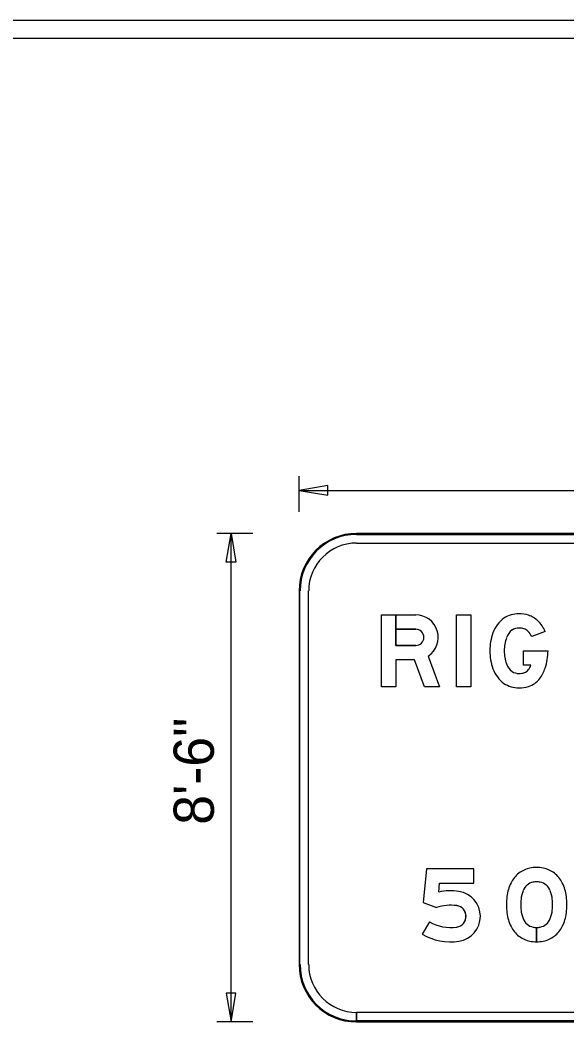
# Model space of a CAD drawing. Extents: x 10268147 to 10268469, y 2141099 to 2141204.
# Drawn here: x 10268267.89 to 10268277.41, y 2141186.52 to 2141203.96 of the extents above; entities that cross this region are included whole.
import ezdxf

# ---------------------------------------------------------------- set-up
doc = ezdxf.new("R2010")
doc.units = 0
for name, color, linetype in [('61', 7, 'Continuous'), ('GSDims', 7, 'Continuous'), ('PlotBorder_dp', 7, 'Continuous'), ('SheetLinesMisc2_dp', 7, 'Continuous')]:
    doc.layers.add(name, color=color, linetype=linetype)

msp = doc.modelspace()

# ---------------------------------------------------------------- linework, layer by layer
at = {"layer": '61'}
msp.add_line((10268230.252, 2141203.638), (10268305.587, 2141203.638), dxfattribs=at)
at = {"layer": 'GSDims'}
for p, q in [((10268272.747, 2141195.396), (10268272.747, 2141196.021)), ((10268272.747, 2141195.771), (10268287.747, 2141195.771)), ((10268271.941, 2141195.021), (10268271.316, 2141195.021)), ((10268271.566, 2141186.521), (10268271.566, 2141195.021)), ((10268271.941, 2141186.521), (10268271.316, 2141186.521))]:
    msp.add_line(p, q, dxfattribs=at)
for points in [[(10268272.747, 2141195.771), (10268273.247, 2141195.688), (10268273.247, 2141195.855)], [(10268271.566, 2141195.021), (10268271.649, 2141194.521), (10268271.482, 2141194.521)], [(10268271.566, 2141186.521), (10268271.649, 2141187.021), (10268271.482, 2141187.021)]]:
    msp.add_lwpolyline(points, close=True, dxfattribs=at)
at = {"layer": 'PlotBorder_dp'}
for p, q in [((10268286.748, 2141195.021), (10268273.748, 2141195.021)), ((10268286.748, 2141195.021), (10268273.748, 2141195.021)), ((10268286.748, 2141195.021), (10268273.748, 2141195.021)), ((10268286.748, 2141195.021), (10268273.748, 2141195.021)), ((10268273.748, 2141195.004), (10268286.748, 2141195.004)), ((10268273.748, 2141194.854), (10268286.748, 2141194.854)), ((10268273.748, 2141194.854), (10268286.748, 2141194.854)), ((10268272.748, 2141194.021), (10268272.748, 2141187.521)), ((10268272.748, 2141194.021), (10268272.748, 2141187.521)), ((10268272.748, 2141194.021), (10268272.748, 2141187.521)), ((10268272.748, 2141194.021), (10268272.748, 2141187.521)), ((10268272.764, 2141187.521), (10268272.764, 2141194.021)), ((10268272.914, 2141187.521), (10268272.914, 2141194.021)), ((10268272.914, 2141187.521), (10268272.914, 2141194.021)), ((10268275.014, 2141188.265), (10268274.889, 2141188.048)), ((10268275.014, 2141188.265), (10268274.889, 2141188.048)), ((10268275.014, 2141188.265), (10268274.889, 2141188.048)), ((10268276.88, 2141188.166), (10268276.88, 2141187.916)), ((10268276.88, 2141187.916), (10268276.88, 2141188.166)), ((10268276.88, 2141188.166), (10268276.88, 2141187.916)), ((10268276.88, 2141187.916), (10268276.88, 2141188.166)), ((10268273.748, 2141186.521), (10268273.748, 2141186.688)), ((10268273.748, 2141186.521), (10268273.748, 2141186.688)), ((10268286.748, 2141186.688), (10268273.749, 2141186.688)), ((10268273.749, 2141186.688), (10268273.749, 2141186.521)), ((10268286.748, 2141186.688), (10268273.749, 2141186.688)), ((10268273.749, 2141186.688), (10268273.749, 2141186.521)), ((10268273.748, 2141186.521), (10268273.748, 2141186.538)), ((10268286.748, 2141186.538), (10268273.748, 2141186.538)), ((10268273.748, 2141186.538), (10268273.748, 2141186.521)), ((10268273.748, 2141186.521), (10268286.748, 2141186.521)), ((10268273.748, 2141186.521), (10268286.748, 2141186.521)), ((10268273.749, 2141186.521), (10268286.748, 2141186.521)), ((10268273.749, 2141186.521), (10268286.748, 2141186.521))]:
    msp.add_line(p, q, dxfattribs=at)
for points in [[(10268274.995, 2141192.888), (10268275.193, 2141192.355), (10268274.927, 2141192.355), (10268274.753, 2141192.822), (10268274.431, 2141192.822), (10268274.431, 2141192.355), (10268274.181, 2141192.355), (10268274.181, 2141193.605), (10268274.431, 2141193.605), (10268274.431, 2141193.072)], [(10268274.995, 2141192.888), (10268275.193, 2141192.355), (10268274.927, 2141192.355), (10268274.753, 2141192.822), (10268274.431, 2141192.822), (10268274.431, 2141192.355), (10268274.181, 2141192.355), (10268274.181, 2141193.605), (10268274.431, 2141193.605), (10268274.431, 2141193.072)], [(10268274.995, 2141192.888), (10268275.193, 2141192.355), (10268274.927, 2141192.355), (10268274.753, 2141192.822), (10268274.431, 2141192.822), (10268274.431, 2141192.355), (10268274.181, 2141192.355), (10268274.181, 2141193.605), (10268274.777, 2141193.605)], [(10268274.777, 2141193.355), (10268274.431, 2141193.355), (10268274.431, 2141193.605), (10268274.777, 2141193.605)], [(10268274.777, 2141193.355), (10268274.431, 2141193.355), (10268274.431, 2141193.605), (10268274.777, 2141193.605)], [(10268274.777, 2141193.072), (10268274.431, 2141193.072), (10268274.431, 2141193.355), (10268274.777, 2141193.355)], [(10268277.028, 2141193.315), (10268276.794, 2141193.226)], [(10268277.028, 2141193.315), (10268276.794, 2141193.226)], [(10268277.028, 2141193.315), (10268276.794, 2141193.226)], [(10268274.431, 2141193.072), (10268274.777, 2141193.072)], [(10268274.431, 2141193.072), (10268274.777, 2141193.072)], [(10268276.78, 2141192.73), (10268276.65, 2141192.73), (10268276.65, 2141192.98), (10268277.078, 2141192.98)], [(10268276.78, 2141192.73), (10268276.65, 2141192.73), (10268276.65, 2141192.98), (10268277.078, 2141192.98)], [(10268276.78, 2141192.73), (10268276.65, 2141192.73), (10268276.65, 2141192.98), (10268277.078, 2141192.98)], [(10268275.177, 2141188.78), (10268275.193, 2141188.937), (10268275.789, 2141188.937), (10268275.789, 2141189.187), (10268274.967, 2141189.187), (10268274.908, 2141188.6), (10268275.138, 2141188.51)], [(10268275.177, 2141188.78), (10268275.193, 2141188.937), (10268275.789, 2141188.937), (10268275.789, 2141189.187), (10268274.967, 2141189.187), (10268274.908, 2141188.6), (10268275.138, 2141188.51)], [(10268275.177, 2141188.78), (10268275.193, 2141188.937), (10268275.789, 2141188.937), (10268275.789, 2141189.187), (10268274.967, 2141189.187), (10268274.908, 2141188.6), (10268275.138, 2141188.51)]]:
    msp.add_lwpolyline(points, dxfattribs=at)
msp.add_lwpolyline([(10268275.484, 2141193.605), (10268275.734, 2141193.605), (10268275.734, 2141192.355), (10268275.484, 2141192.355)], close=True, dxfattribs=at)
msp.add_lwpolyline([(10268275.484, 2141193.605), (10268275.734, 2141193.605), (10268275.734, 2141192.355), (10268275.484, 2141192.355)], close=True, dxfattribs=at)
msp.add_lwpolyline([(10268275.484, 2141193.605), (10268275.734, 2141193.605), (10268275.734, 2141192.355), (10268275.484, 2141192.355)], close=True, dxfattribs=at)
for centre, radius, start, end in [((10268273.748, 2141194.021), 1, 90, 180), ((10268273.748, 2141194.021), 1, 90, 180), ((10268273.748, 2141194.021), 1, 90, 180), ((10268273.748, 2141194.021), 1, 90, 180), ((10268273.748, 2141194.021), 0.983, 90, 180), ((10268273.748, 2141194.021), 0.833, 90, 180), ((10268273.748, 2141194.021), 0.833, 90, 180), ((10268273.748, 2141187.521), 1, 180, 270), ((10268273.748, 2141187.521), 1, 180, 270), ((10268273.748, 2141187.521), 1, 180, 270), ((10268273.748, 2141187.521), 1, 180, 270), ((10268273.748, 2141187.521), 0.983, 180, 270), ((10268273.748, 2141187.521), 0.833, 180, 270), ((10268273.748, 2141187.521), 0.833, 180, 270)]:
    msp.add_arc(centre, radius, start, end, dxfattribs=at)
for centre, major_axis, ratio, start_param, end_param in [((10268274.777, 2141193.213), (0, 0.391), 0.999998, 3.731228, 6.283185), ((10268274.777, 2141193.213), (0, 0.391), 0.999998, 3.731228, 6.283185), ((10268274.777, 2141193.213), (0, 0.391), 0.999998, 3.731228, 6.283185), ((10268276.634, 2141193.109), (0, 0.545), 0.999996, 0.634329, 1.227998), ((10268276.634, 2141193.109), (0, 0.545), 0.999996, 0.634329, 1.227998), ((10268276.634, 2141193.109), (0, 0.545), 0.999996, 0.634329, 1.227998), ((10268276.571, 2141193.145), (0, 0.479), 0.999996, 6.282946, 6.85835), ((10268276.571, 2141193.145), (0, 0.479), 0.999996, 6.282946, 6.85835), ((10268276.571, 2141193.145), (0, 0.479), 0.999996, 6.282946, 6.85835), ((10268276.571, 2141193.087), (0, 0.537), 0.999996, 5.968128, 6.283185), ((10268276.571, 2141193.087), (0, 0.537), 0.999996, 5.968128, 6.283185), ((10268276.571, 2141193.087), (0, 0.537), 0.999996, 5.968128, 6.283185), ((10268276.606, 2141193.194), (0, 0.425), 0.999996, 5.51497, 5.968128), ((10268276.606, 2141193.194), (0, 0.425), 0.999996, 5.51497, 5.968128), ((10268276.606, 2141193.194), (0, 0.425), 0.999996, 5.51497, 5.968128), ((10268276.571, 2141193.145), (0, 0.229), 0.999996, 6.282815, 6.826868), ((10268276.571, 2141193.145), (0, 0.229), 0.999996, 6.282815, 6.826868), ((10268276.571, 2141193.145), (0, 0.229), 0.999996, 6.282815, 6.826868), ((10268276.571, 2141193.087), (0, 0.287), 0.999996, 5.968128, 6.283185), ((10268276.571, 2141193.087), (0, 0.287), 0.999996, 5.968128, 6.283185), ((10268276.571, 2141193.087), (0, 0.287), 0.999996, 5.968128, 6.283185), ((10268276.513, 2141193.097), (0, 0.559), 0.999996, 5.112302, 5.51497), ((10268276.513, 2141193.097), (0, 0.559), 0.999996, 5.112302, 5.51497), ((10268276.513, 2141193.097), (0, 0.559), 0.999996, 5.112302, 5.51497), ((10268274.777, 2141193.213), (0, 0.141), 0.999998, 3.141593, 6.283185), ((10268274.777, 2141193.213), (0, 0.141), 0.999998, 3.141593, 6.283185), ((10268274.777, 2141193.213), (0, 0.141), 0.999998, 3.141593, 6.283185), ((10268277.053, 2141192.965), (0, 0.988), 0.999996, 1.233536, 1.555728), ((10268277.053, 2141192.965), (0, 0.988), 0.999996, 1.233536, 1.555728), ((10268277.053, 2141192.965), (0, 0.988), 0.999996, 1.233536, 1.555728), ((10268276.998, 2141192.979), (0, 0.681), 0.999996, 1.228714, 1.570494), ((10268276.998, 2141192.979), (0, 0.681), 0.999996, 1.228714, 1.570494), ((10268276.998, 2141192.979), (0, 0.681), 0.999996, 1.228714, 1.570494), ((10268276.634, 2141193.109), (0, 0.295), 0.999996, 0.660238, 1.227998), ((10268276.634, 2141193.109), (0, 0.295), 0.999996, 0.660238, 1.227998), ((10268276.634, 2141193.109), (0, 0.295), 0.999996, 0.660238, 1.227998), ((10268276.606, 2141193.194), (0, 0.175), 0.999996, 5.51497, 5.968128), ((10268276.606, 2141193.194), (0, 0.175), 0.999996, 5.51497, 5.968128), ((10268276.606, 2141193.194), (0, 0.175), 0.999996, 5.51497, 5.968128), ((10268276.513, 2141193.097), (0, 0.309), 0.999996, 5.141395, 5.51497), ((10268276.513, 2141193.097), (0, 0.309), 0.999996, 5.141395, 5.51497), ((10268276.513, 2141193.097), (0, 0.309), 0.999996, 5.141395, 5.51497), ((10268277.053, 2141192.994), (0, 0.988), 0.999996, 1.585865, 1.908057), ((10268277.053, 2141192.994), (0, 0.988), 0.999996, 1.585865, 1.908057), ((10268277.053, 2141192.994), (0, 0.988), 0.999996, 1.585865, 1.908057), ((10268276.997, 2141192.98), (0, 0.681), 0.999996, 1.571362, 1.913142), ((10268276.997, 2141192.98), (0, 0.681), 0.999996, 1.571362, 1.913142), ((10268276.997, 2141192.98), (0, 0.681), 0.999996, 1.571362, 1.913142), ((10268276.163, 2141192.98), (0, 0.915), 0.999996, 4.373891, 4.712389), ((10268276.163, 2141192.98), (0, 0.915), 0.999996, 4.373891, 4.712389), ((10268276.163, 2141192.98), (0, 0.915), 0.999996, 4.373891, 4.712389), ((10268276.633, 2141192.85), (0, 0.294), 0.999996, 1.913852, 2.481612), ((10268276.633, 2141192.85), (0, 0.294), 0.999996, 1.913852, 2.481612), ((10268276.633, 2141192.85), (0, 0.294), 0.999996, 1.913852, 2.481612), ((10268276.462, 2141192.849), (0, 0.34), 0.999996, 4.071542, 4.353904), ((10268276.462, 2141192.849), (0, 0.34), 0.999996, 4.071542, 4.353904), ((10268276.462, 2141192.849), (0, 0.34), 0.999996, 4.071542, 4.353904), ((10268276.462, 2141192.849), (0, 0.59), 0.999996, 4.071542, 4.414751), ((10268276.462, 2141192.849), (0, 0.59), 0.999996, 4.071542, 4.414751), ((10268276.462, 2141192.849), (0, 0.59), 0.999996, 4.071542, 4.414751), ((10268276.634, 2141192.85), (0, 0.545), 0.999996, 1.913595, 2.507264), ((10268276.634, 2141192.85), (0, 0.545), 0.999996, 1.913595, 2.507264), ((10268276.634, 2141192.85), (0, 0.545), 0.999996, 1.913595, 2.507264), ((10268276.571, 2141192.814), (0, 0.229), 0.999996, 2.597779, 3.141832), ((10268276.571, 2141192.814), (0, 0.229), 0.999996, 2.597779, 3.141832), ((10268276.571, 2141192.814), (0, 0.229), 0.999996, 2.597779, 3.141832), ((10268276.571, 2141192.919), (0, 0.334), 0.999996, 3.141503, 3.435382), ((10268276.571, 2141192.919), (0, 0.334), 0.999996, 3.141503, 3.435382), ((10268276.571, 2141192.919), (0, 0.334), 0.999996, 3.141503, 3.435382), ((10268276.631, 2141192.723), (0, 0.129), 0.999996, 3.435472, 4.071542), ((10268276.631, 2141192.723), (0, 0.129), 0.999996, 3.435472, 4.071542), ((10268276.631, 2141192.723), (0, 0.129), 0.999996, 3.435472, 4.071542), ((10268276.631, 2141192.723), (0, 0.379), 0.999996, 3.435472, 4.071542), ((10268276.631, 2141192.723), (0, 0.379), 0.999996, 3.435472, 4.071542), ((10268276.631, 2141192.723), (0, 0.379), 0.999996, 3.435472, 4.071542), ((10268276.571, 2141192.814), (0, 0.479), 0.999996, 2.566428, 3.141832), ((10268276.571, 2141192.814), (0, 0.479), 0.999996, 2.566428, 3.141832), ((10268276.571, 2141192.814), (0, 0.479), 0.999996, 2.566428, 3.141832), ((10268276.571, 2141192.919), (0, 0.584), 0.999996, 3.141593, 3.435472), ((10268276.571, 2141192.919), (0, 0.584), 0.999996, 3.141593, 3.435472), ((10268276.571, 2141192.919), (0, 0.584), 0.999996, 3.141593, 3.435472), ((10268276.856, 2141188.742), (0, 0.465), 0.999999, 0.198221, 0.659474), ((10268276.856, 2141188.742), (0, 0.465), 0.999999, 0.198221, 0.659474), ((10268276.856, 2141188.742), (0, 0.465), 0.999999, 0.198221, 0.659474), ((10268276.88, 2141188.619), (0, 0.59), 0.999999, 0, 0.197523), ((10268276.88, 2141188.619), (0, 0.59), 0.999999, 0, 0.197523), ((10268276.88, 2141188.619), (0, 0.59), 0.999999, 0, 0.197523), ((10268276.88, 2141188.619), (0, 0.59), 0.999999, 6.085662, 6.283185), ((10268276.88, 2141188.619), (0, 0.59), 0.999999, 6.085662, 6.283185), ((10268276.88, 2141188.619), (0, 0.59), 0.999999, 6.085662, 6.283185), ((10268276.904, 2141188.742), (0, 0.465), 0.999999, 5.623711, 6.084964), ((10268276.904, 2141188.742), (0, 0.465), 0.999999, 5.623711, 6.084964), ((10268276.904, 2141188.742), (0, 0.465), 0.999999, 5.623711, 6.084964), ((10268276.883, 2141188.716), (0, 0.502), 0.999999, 0.670985, 1.104331), ((10268276.883, 2141188.716), (0, 0.502), 0.999999, 0.670985, 1.104331), ((10268276.883, 2141188.716), (0, 0.502), 0.999999, 0.670985, 1.104331), ((10268276.877, 2141188.716), (0, 0.502), 0.999999, 5.178855, 5.6122), ((10268276.877, 2141188.716), (0, 0.502), 0.999999, 5.178855, 5.6122), ((10268276.877, 2141188.716), (0, 0.502), 0.999999, 5.178855, 5.6122), ((10268277.09, 2141188.614), (0, 0.732), 0.999999, 1.107023, 1.446049), ((10268277.09, 2141188.614), (0, 0.732), 0.999999, 1.107023, 1.446049), ((10268277.09, 2141188.614), (0, 0.732), 0.999999, 1.107023, 1.446049), ((10268276.889, 2141188.706), (0, 0.265), 0.999999, 0.724344, 1.185227), ((10268276.889, 2141188.706), (0, 0.265), 0.999999, 0.724344, 1.185227), ((10268276.889, 2141188.706), (0, 0.265), 0.999999, 0.724344, 1.185227), ((10268276.86, 2141188.731), (0, 0.226), 0.999999, 0.192068, 0.701922), ((10268276.86, 2141188.731), (0, 0.226), 0.999999, 0.192068, 0.701922), ((10268276.86, 2141188.731), (0, 0.226), 0.999999, 0.192068, 0.701922), ((10268276.88, 2141188.627), (0, 0.332), 0.999999, 0, 0.192642), ((10268276.88, 2141188.627), (0, 0.332), 0.999999, 0, 0.192642), ((10268276.88, 2141188.627), (0, 0.332), 0.999999, 0, 0.192642), ((10268276.88, 2141188.627), (0, 0.332), 0.999999, 6.090544, 6.283185), ((10268276.88, 2141188.627), (0, 0.332), 0.999999, 6.090544, 6.283185), ((10268276.88, 2141188.627), (0, 0.332), 0.999999, 6.090544, 6.283185), ((10268276.9, 2141188.731), (0, 0.226), 0.999999, 5.581263, 6.091117), ((10268276.9, 2141188.731), (0, 0.226), 0.999999, 5.581263, 6.091117), ((10268276.9, 2141188.731), (0, 0.226), 0.999999, 5.581263, 6.091117), ((10268276.871, 2141188.706), (0, 0.265), 0.999999, 5.097959, 5.558841), ((10268276.871, 2141188.706), (0, 0.265), 0.999999, 5.097959, 5.558841), ((10268276.871, 2141188.706), (0, 0.265), 0.999999, 5.097959, 5.558841), ((10268276.671, 2141188.614), (0, 0.732), 0.999999, 4.837137, 5.176162), ((10268276.671, 2141188.614), (0, 0.732), 0.999999, 4.837137, 5.176162), ((10268276.671, 2141188.614), (0, 0.732), 0.999999, 4.837137, 5.176162), ((10268275.384, 2141187.812), (0, 0.991), 0.999999, 6.137785, 6.493274), ((10268275.384, 2141187.812), (0, 0.991), 0.999999, 6.137785, 6.493274), ((10268275.384, 2141187.812), (0, 0.991), 0.999999, 6.137785, 6.493274), ((10268275.464, 2141188.359), (0, 0.437), 0.999999, 3.286993, 6.137785), ((10268275.464, 2141188.359), (0, 0.437), 0.999999, 3.286993, 6.137785), ((10268275.464, 2141188.359), (0, 0.437), 0.999999, 3.286993, 6.137785), ((10268277.648, 2141188.562), (0, 1.293), 0.999999, 1.459794, 1.570796), ((10268277.648, 2141188.562), (0, 1.293), 0.999999, 1.459794, 1.570796), ((10268277.648, 2141188.562), (0, 1.293), 0.999999, 1.459794, 1.570796), ((10268277.118, 2141188.613), (0, 0.511), 0.999999, 1.185935, 1.48488), ((10268277.118, 2141188.613), (0, 0.511), 0.999999, 1.185935, 1.48488), ((10268277.118, 2141188.613), (0, 0.511), 0.999999, 1.185935, 1.48488), ((10268276.643, 2141188.613), (0, 0.511), 0.999999, 4.798305, 5.09725), ((10268276.643, 2141188.613), (0, 0.511), 0.999999, 4.798305, 5.09725), ((10268276.643, 2141188.613), (0, 0.511), 0.999999, 4.798305, 5.09725), ((10268276.112, 2141188.562), (0, 1.293), 0.999999, 4.712389, 4.823392), ((10268276.112, 2141188.562), (0, 1.293), 0.999999, 4.712389, 4.823392), ((10268276.112, 2141188.562), (0, 1.293), 0.999999, 4.712389, 4.823392), ((10268275.384, 2141187.812), (0, 0.741), 0.999999, 6.137785, 6.621752), ((10268275.384, 2141187.812), (0, 0.741), 0.999999, 6.137785, 6.621752), ((10268275.384, 2141187.812), (0, 0.741), 0.999999, 6.137785, 6.621752), ((10268275.464, 2141188.359), (0, 0.187), 0.999999, 3.286993, 6.137785), ((10268275.464, 2141188.359), (0, 0.188), 0.999999, 3.286993, 6.137785), ((10268275.464, 2141188.359), (0, 0.188), 0.999999, 3.286993, 6.137785), ((10268277.648, 2141188.562), (0, 1.293), 0.999999, 1.570796, 1.681799), ((10268277.648, 2141188.562), (0, 1.293), 0.999999, 1.570796, 1.681799), ((10268277.648, 2141188.562), (0, 1.293), 0.999999, 1.570796, 1.681799), ((10268278.022, 2141188.562), (0, 1.417), 0.999999, 1.503921, 1.570796), ((10268278.022, 2141188.562), (0, 1.417), 0.999999, 1.503921, 1.570796), ((10268278.022, 2141188.562), (0, 1.417), 0.999999, 1.503921, 1.570796), ((10268278.022, 2141188.562), (0, 1.417), 0.999999, 1.570796, 1.637672), ((10268278.022, 2141188.562), (0, 1.417), 0.999999, 1.570796, 1.637672), ((10268278.022, 2141188.562), (0, 1.417), 0.999999, 1.570796, 1.637672), ((10268275.738, 2141188.562), (0, 1.417), 0.999999, 4.712389, 4.779265), ((10268275.738, 2141188.562), (0, 1.417), 0.999999, 4.712389, 4.779265), ((10268275.738, 2141188.562), (0, 1.417), 0.999999, 4.712389, 4.779265), ((10268275.738, 2141188.562), (0, 1.417), 0.999999, 4.645513, 4.712389), ((10268275.738, 2141188.562), (0, 1.417), 0.999999, 4.645513, 4.712389), ((10268275.738, 2141188.562), (0, 1.417), 0.999999, 4.645513, 4.712389), ((10268276.112, 2141188.562), (0, 1.293), 0.999999, 4.601386, 4.712389), ((10268276.112, 2141188.562), (0, 1.293), 0.999999, 4.601386, 4.712389), ((10268276.112, 2141188.562), (0, 1.293), 0.999999, 4.601386, 4.712389), ((10268277.09, 2141188.51), (0, 0.732), 0.999999, 1.695544, 2.03457), ((10268277.09, 2141188.51), (0, 0.732), 0.999999, 1.695544, 2.03457), ((10268277.09, 2141188.51), (0, 0.732), 0.999999, 1.695544, 2.03457), ((10268277.118, 2141188.512), (0, 0.511), 0.999999, 1.656712, 1.955657), ((10268277.118, 2141188.512), (0, 0.511), 0.999999, 1.656712, 1.955657), ((10268277.118, 2141188.512), (0, 0.511), 0.999999, 1.656712, 1.955657), ((10268276.889, 2141188.419), (0, 0.265), 0.999999, 1.956366, 2.417249), ((10268276.889, 2141188.419), (0, 0.265), 0.999999, 1.956366, 2.417249), ((10268276.889, 2141188.419), (0, 0.265), 0.999999, 1.956366, 2.417249), ((10268276.871, 2141188.419), (0, 0.265), 0.999999, 3.865937, 4.326819), ((10268276.871, 2141188.419), (0, 0.265), 0.999999, 3.865937, 4.326819), ((10268276.871, 2141188.419), (0, 0.265), 0.999999, 3.865937, 4.326819), ((10268276.643, 2141188.512), (0, 0.511), 0.999999, 4.327528, 4.626473), ((10268276.643, 2141188.512), (0, 0.511), 0.999999, 4.327528, 4.626473), ((10268276.643, 2141188.512), (0, 0.511), 0.999999, 4.327528, 4.626473), ((10268276.671, 2141188.51), (0, 0.732), 0.999999, 4.248616, 4.587641), ((10268276.671, 2141188.51), (0, 0.732), 0.999999, 4.248616, 4.587641), ((10268276.671, 2141188.51), (0, 0.732), 0.999999, 4.248616, 4.587641), ((10268275.384, 2141188.906), (0, 0.741), 0.999999, 2.618523, 3.286993), ((10268275.384, 2141188.906), (0, 0.741), 0.999999, 2.618523, 3.286993), ((10268275.384, 2141188.906), (0, 0.741), 0.999999, 2.618523, 3.286993), ((10268276.883, 2141188.408), (0, 0.502), 0.999999, 2.037262, 2.470608), ((10268276.883, 2141188.408), (0, 0.502), 0.999999, 2.037262, 2.470608), ((10268276.883, 2141188.408), (0, 0.502), 0.999999, 2.037262, 2.470608), ((10268276.86, 2141188.394), (0, 0.226), 0.999999, 2.43967, 2.949524), ((10268276.86, 2141188.394), (0, 0.226), 0.999999, 2.43967, 2.949524), ((10268276.86, 2141188.394), (0, 0.226), 0.999999, 2.43967, 2.949524), ((10268276.88, 2141188.497), (0, 0.332), 0.999999, 2.948951, 3.141593), ((10268276.88, 2141188.497), (0, 0.332), 0.999999, 2.948951, 3.141593), ((10268276.88, 2141188.497), (0, 0.332), 0.999999, 2.948951, 3.141593), ((10268276.88, 2141188.497), (0, 0.332), 0.999999, 3.141593, 3.334234), ((10268276.88, 2141188.497), (0, 0.332), 0.999999, 3.141781, 3.334234), ((10268276.88, 2141188.497), (0, 0.332), 0.999999, 3.141781, 3.334234), ((10268276.9, 2141188.394), (0, 0.226), 0.999999, 3.333661, 3.843515), ((10268276.9, 2141188.394), (0, 0.226), 0.999999, 3.333661, 3.843515), ((10268276.9, 2141188.394), (0, 0.226), 0.999999, 3.333661, 3.843515), ((10268276.877, 2141188.408), (0, 0.502), 0.999999, 3.812578, 4.245923), ((10268276.877, 2141188.408), (0, 0.502), 0.999999, 3.812578, 4.245923), ((10268276.877, 2141188.408), (0, 0.502), 0.999999, 3.812578, 4.245923), ((10268275.384, 2141188.906), (0, 0.991), 0.999999, 2.618523, 3.286993), ((10268275.384, 2141188.906), (0, 0.991), 0.999999, 2.618523, 3.286993), ((10268275.384, 2141188.906), (0, 0.991), 0.999999, 2.618523, 3.286993), ((10268276.856, 2141188.383), (0, 0.465), 0.999999, 2.482119, 2.943371), ((10268276.856, 2141188.383), (0, 0.465), 0.999999, 2.482119, 2.943371), ((10268276.856, 2141188.383), (0, 0.465), 0.999999, 2.482119, 2.943371), ((10268276.904, 2141188.383), (0, 0.465), 0.999999, 3.339814, 3.801066), ((10268276.904, 2141188.383), (0, 0.465), 0.999999, 3.339814, 3.801066), ((10268276.904, 2141188.383), (0, 0.465), 0.999999, 3.339814, 3.801066), ((10268276.88, 2141188.506), (0, 0.59), 0.999999, 2.94407, 3.141593), ((10268276.88, 2141188.506), (0, 0.59), 0.999999, 2.94407, 3.141593), ((10268276.88, 2141188.506), (0, 0.59), 0.999999, 2.94407, 3.141593), ((10268276.88, 2141188.506), (0, 0.59), 0.999999, 3.141593, 3.339116), ((10268276.88, 2141188.506), (0, 0.59), 0.999999, 3.141699, 3.339116), ((10268276.88, 2141188.506), (0, 0.59), 0.999999, 3.141699, 3.339116)]:
    msp.add_ellipse(centre, major_axis=major_axis, ratio=ratio, start_param=start_param, end_param=end_param, dxfattribs=at)
at = {"layer": 'SheetLinesMisc2_dp'}
msp.add_line((10268153.14, 2141203.955), (10268306.32, 2141203.955), dxfattribs=at)

# ---------------------------------------------------------------- texts
at = {"layer": 'GSDims'}
msp.add_text('8\'-6"', height=0.7, rotation=90, dxfattribs=at).set_placement((10268271.266, 2141189.951))

doc.saveas('drawing.dxf')
